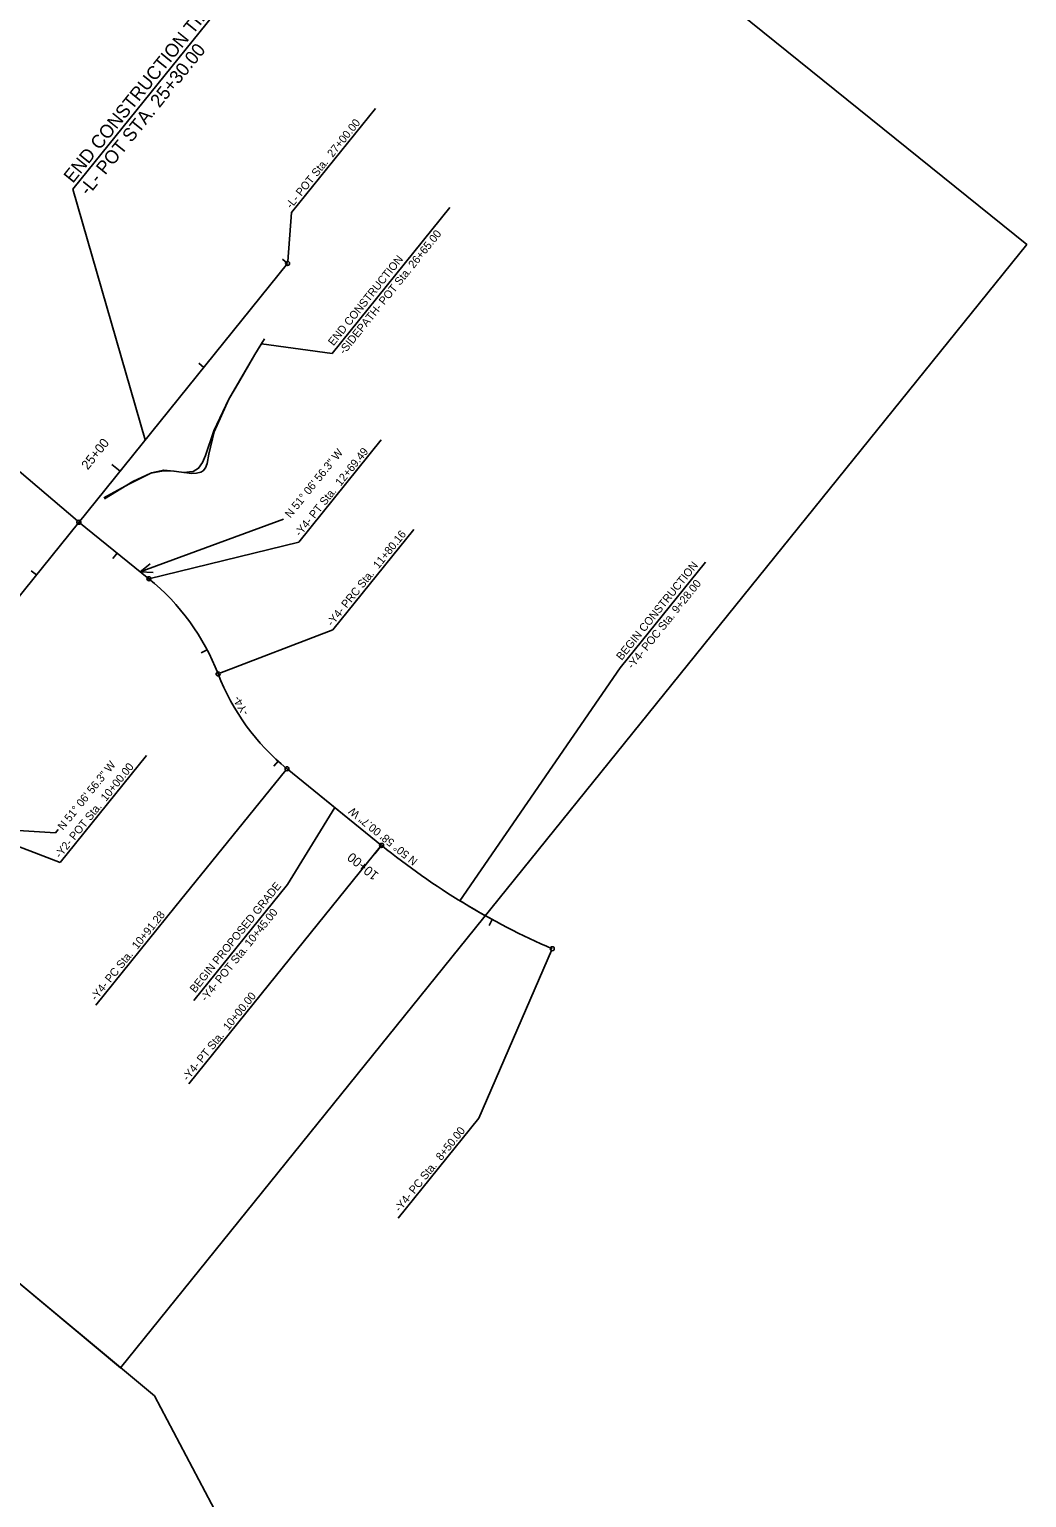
# Model space of a CAD drawing. Extents: x 1487008 to 1489561, y 497293 to 500195.
# Drawn here: x 1488814 to 1489561, y 498527 to 499628 of the extents above; entities that cross this region are included whole.
import ezdxf

# ---------------------------------------------------------------- set-up
doc = ezdxf.new("R2010")
doc.units = 0
for name, color, linetype in [('Prop Horizontal Alignment', 7, 'Continuous'), ('Prop Horizontal Alignment Direction Label', 7, 'Continuous'), ('Prop Horizontal Alignment Point', 7, 'Continuous'), ('Prop Horizontal Alignment Station Label', 7, 'Continuous'), ('Prop Horizontal Alignment Tick Label', 7, 'Continuous'), ('Prop Horizontal Alignment Tick Large', 7, 'Continuous'), ('Prop Horizontal Alignment Tick Small', 7, 'Continuous'), ('Scratch_Level_2', 7, 'Continuous'), ('Scratch_Level_3', 7, 'Continuous'), ('Scratch_Level_5', 7, 'Continuous')]:
    doc.layers.add(name, color=color, linetype=linetype)

msp = doc.modelspace()

# ---------------------------------------------------------------- linework, layer by layer
at = {"layer": 'Prop Horizontal Alignment'}
for p, q in [((1488573.1, 498913.9), (1489007.3, 499452.3)), ((1488903.3, 499215.9), (1488850.8, 499258.2)), ((1489077.8, 499016), (1489006.9, 499073.4)), ((1489077.8, 499016), (1489032.5, 499052.7))]:
    msp.add_line(p, q, dxfattribs=at)
for centre, radius, start, end in [((1488796.5, 499083.6), 170, 21.0099, 51.1156), ((1489113.9, 499205.5), 170, 201.0099, 230.9669), ((1489424.2, 499443.2), 550, 230.9669, 246.593)]:
    msp.add_arc(centre, radius, start, end, dxfattribs=at)
at = {"layer": 'Prop Horizontal Alignment Direction Label'}
for p in [(1488779.7, 499028.8), (1488835.2, 499027.9)]:
    msp.add_line(p, (1488833.2, 499025.4), dxfattribs=at)
at = {"layer": 'Prop Horizontal Alignment Point'}
for p, q in [((1489040.7, 499384.8), (1489129, 499494.3)), ((1488987.7, 499392.1), (1489040.7, 499384.8))]:
    msp.add_line(p, q, dxfattribs=at)
at = {"layer": 'Prop Horizontal Alignment Station Label'}
for p, q in [((1488846.3, 499507.9), (1488995, 499692.2)), ((1489010.3, 499490.5), (1489073.2, 499568.4)), ((1488900.6, 499320), (1488846.3, 499507.9)), ((1489007.5, 499453.8), (1489010.3, 499490.5)), ((1488740.7, 499352.4), (1488849.7, 499259.2)), ((1489015.7, 499243.4), (1489077.5, 499320.1)), ((1488896.9, 499221), (1489004.1, 499260.6)), ((1489041.1, 499177.5), (1489101.9, 499252.9)), ((1488903.3, 499215.9), (1489015.7, 499243.4)), ((1488904.4, 499227), (1488896.9, 499221)), ((1489256.6, 499149), (1489320.6, 499228.3)), ((1488906.5, 499220.7), (1488896.9, 499221)), ((1488956.6, 499145.1), (1489041.1, 499177.5)), ((1489136.5, 498974.4), (1489256.6, 499149)), ((1488836.7, 499003.1), (1488901.6, 499083.5)), ((1489005.9, 499072.3), (1488922.8, 498969.7)), ((1489042.8, 499044.3), (1489007.1, 498986.7)), ((1488788.6, 499021.7), (1488836.7, 499003.1)), ((1489076.8, 499014.8), (1488993.7, 498912.2)), ((1488936.9, 498899.7), (1489007.1, 498986.7)), ((1488863.5, 498896.2), (1488922.8, 498969.7)), ((1489205.1, 498937.1), (1489150.7, 498811.6)), ((1488933.2, 498837.3), (1488993.7, 498912.2)), ((1489090.3, 498736.6), (1489150.7, 498811.6))]:
    msp.add_line(p, q, dxfattribs=at)
for centre in [(1489007.3, 499452.3), (1488850.8, 499258.2), (1488850.8, 499258.2), (1488903.3, 499215.9), (1488955.2, 499144.5), (1489006.9, 499073.4), (1489077.8, 499016), (1489205.7, 498938.5)]:
    msp.add_circle(centre, 1.5, dxfattribs=at)
at = {"layer": 'Prop Horizontal Alignment Tick Large'}
for p, q in [((1488881.8, 499296.6), (1488875.6, 499301.6)), ((1489077.8, 499016), (1489072.7, 499009.7))]:
    msp.add_line(p, q, dxfattribs=at)
at = {"layer": 'Prop Horizontal Alignment Tick Small'}
for p, q in [((1489007.3, 499452.3), (1489003.4, 499455.4)), ((1488944.6, 499374.4), (1488940.7, 499377.6)), ((1488879.5, 499235.1), (1488876.4, 499231.2)), ((1488819, 499218.8), (1488815.1, 499221.9)), ((1488947.1, 499162.6), (1488942.6, 499160.3)), ((1489000.3, 499079.1), (1488996.9, 499075.4)), ((1489160.7, 498960.4), (1489158.4, 498956))]:
    msp.add_line(p, q, dxfattribs=at)
at = {"layer": 'Scratch_Level_2'}
msp.add_arc((1489424.2, 499443.2), 550, 238.4674, 241.3843, dxfattribs=at)
at = {"layer": 'Scratch_Level_3'}
msp.add_lwpolyline([(1488869.5, 499276.5), (1488888.2, 499286.8), (1488905.2, 499295.3), (1488914.4, 499297.4), (1488922.1, 499296.6), (1488935.5, 499294.9), (1488939, 499295.1), (1488942.3, 499295.7), (1488943.9, 499296.7), (1488945.8, 499299), (1488946.9, 499302.4), (1488948.3, 499309.2), (1488952.2, 499326.1), (1488963.2, 499350.5), (1488970.4, 499362.7), (1488982.7, 499383.9), (1488989.9, 499395.7)], dxfattribs=at)
at = {"layer": 'Scratch_Level_5'}
for p, q in [((1488882.1, 498624.3), (1488075.1, 499296.3)), ((1488907.6, 498603.2), (1488170.1, 499217.2))]:
    msp.add_line(p, q, dxfattribs=at)
for points in [[(1488075.1, 499296.3), (1488618.3, 499969.9), (1488753.4, 499860.9), (1488879, 500016.6), (1489561.3, 499466.4), (1488882.1, 498624.3), (1488882.1, 498624.3)], [(1488870, 499275.9), (1488891.3, 499288.8), (1488904.8, 499295.1), (1488914.2, 499296.8), (1488922.3, 499296.5), (1488929.4, 499295.5), (1488933.8, 499296), (1488936.5, 499296.4), (1488940.6, 499298.8), (1488943.6, 499303), (1488945.7, 499308.3), (1488951.9, 499326.9), (1488963.2, 499350.6), (1488971.2, 499364.2), (1488982.8, 499384), (1488988.2, 499392.9)], [(1488170.1, 499217.2), (1487167.7, 498687.9), (1487657.1, 497758.9), (1488983.5, 498459.3), (1488907.6, 498603.2)]]:
    msp.add_lwpolyline(points, dxfattribs=at)

# ---------------------------------------------------------------- texts
at = {"layer": 'Prop Horizontal Alignment Direction Label'}
for s, rotation, p in [('-Y4-', 119.8435, (1488978.5, 499115.5)), ('N 51%%d 06\' 56.3" W', 51.1156, (1488839, 499026.9)), ('N 50%%d 58\' 00.7" W', 140.9669, (1489105.3, 499005.1))]:
    msp.add_text(s, height=6, rotation=rotation, dxfattribs=at).set_placement(p)
at = {"layer": 'Prop Horizontal Alignment Point'}
for s, p in [('-SIDEPATH- POT Sta. 26+65.00', (1489049.8, 499383.6)), ('END CONSTRUCTION', (1489041.7, 499390.1))]:
    msp.add_text(s, height=6, rotation=51.1156, dxfattribs=at).set_placement(p)
at = {"layer": 'Prop Horizontal Alignment Station Label'}
for s, height, rotation, p in [('END CONSTRUCTION TIP HL-0025', 10, 51.1156, (1488846.3, 499511.9)), ('-L- POT STA. 25+30.00', 10, 51.1156, (1488858, 499502.5)), ('-L- POT Sta.  27+00.00', 6, 51.1156, (1489010, 499492.9)), ('N 51%%d 06\' 56.3" W', 6, 51.0874, (1489009.4, 499261)), ('-Y4- PT Sta.  12+69.49', 6, 51.1156, (1489016.6, 499247.1)), ('-Y4- PRC Sta.  11+80.16', 6, 51.1156, (1489040.7, 499179.9)), ('BEGIN CONSTRUCTION', 6, 51.1156, (1489257.7, 499154.3)), ('-Y4- POC Sta. 9+28.00', 6, 51.1156, (1489265.8, 499147.8)), ('-Y2- POT Sta.  10+00.00', 6, 51.1156, (1488836.8, 499005.9)), ('BEGIN PROPOSED GRADE', 6, 51.1156, (1488938, 498905)), ('-Y4- PC Sta.  10+91.28', 6, 51.1156, (1488863.6, 498899.1)), ('-Y4- POT Sta. 10+45.00', 6, 51.1156, (1488946.1, 498898.5)), ('-Y4- PT Sta.  10+00.00', 6, 51.1156, (1488932.4, 498838.9)), ('-Y4- PC Sta.  8+50.00', 6, 51.1156, (1489091.4, 498740.7))]:
    msp.add_text(s, height=height, rotation=rotation, dxfattribs=at).set_placement(p)
at = {"layer": 'Prop Horizontal Alignment Tick Label'}
for s, rotation, p in [('25+00', 51.1156, (1488857.5, 499297.1)), ('10+00', 140.9858, (1489076.1, 498994.6))]:
    msp.add_text(s, height=7, rotation=rotation, dxfattribs=at).set_placement(p)

doc.saveas('drawing.dxf')
